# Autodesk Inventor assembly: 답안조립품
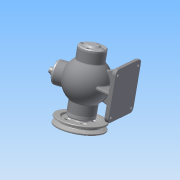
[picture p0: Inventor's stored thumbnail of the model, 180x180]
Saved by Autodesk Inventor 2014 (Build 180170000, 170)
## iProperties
Created: 2017-01
Part Number: 답안조립품
Document SubType Name: Assembly
Designer: ksu
Author: ksu
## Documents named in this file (19)
- C:\Users\ksu\Desktop\470118V1008\답안조립품.iam
- C:\Users\ksu\Desktop\470118V1008\1.본체.ipt
- C:\Users\ksu\Desktop\470118V1008\V-벨트풀리.ipt
- C:\Users\ksu\Desktop\470118V1008\너트 M8.ipt
- C:\Users\ksu\Desktop\470118V1008\뒤커버.ipt
- C:\Users\ksu\Desktop\470118V1008\멈춤링- 15 x 1.ipt
- C:\Users\ksu\Desktop\470118V1008\멈춤링- 35x1.6.ipt
- KS B 1336 - 35x1.6.ipt
- C:\Users\ksu\Desktop\470118V1008\베어링- 6202.ipt
- KS B 2023 - 6202 - 15 x 35 x 11 - 7.8.ipt
- C:\Users\ksu\Desktop\470118V1008\볼트 M4 x 12.ipt
- C:\Users\ksu\Desktop\470118V1008\볼트 M4 x 16.ipt
- C:\Users\ksu\Desktop\470118V1008\부시.ipt
- C:\Users\ksu\Desktop\470118V1008\상부커버.ipt
- C:\Users\ksu\Desktop\470118V1008\슬라이드.ipt
- C:\Users\ksu\Desktop\470118V1008\앞커버.ipt
- C:\Users\ksu\Desktop\470118V1008\오일실 15 30 7.ipt
- C:\Users\ksu\Desktop\470118V1008\키 4 x 4 x 12.ipt
- C:\Users\ksu\Desktop\470118V1008\편심축.ipt
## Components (17 placed, 6 different names)
1. 1.본체:1 — Mate:13, Mate:14, Mate:15, Mate:16, Mate:20, Mate:21, Mate:22, Mate:23, Mate:24, Mate:25, Mate:26, Mate:27
2. V-벨트풀리:1 — Mate:11, Mate:12, Mate:28, Mate:30
3. KS B 1336 - 35x1.6:1 — Mate:14, Mate:15, Mate:17
4. KS B 2023 - 6202 - 15 x 35 x 11 - 7.8:1 — Mate:5, Mate:6, Mate:8
5. KS B 1021 - 에 따름 ISO 1207 - 미터 A  M 4 x 12:1 — Insert:12
6. ISO 4762 M4 x 16:1 — Insert:2
7. KS B 2023 - 6202 - 15 x 35 x 11 - 7.8:2 — Mate:16, Mate:17, Mate:18, Mate:19
8. ISO 4762 M4 x 16:2 — Insert:3
9. ISO 4762 M4 x 16:3 — Insert:1
10. ISO 4762 M4 x 16:4 — Insert:4
11. ISO 4762 M4 x 16:5 — Insert:5
12. ISO 4762 M4 x 16:6 — Insert:6
13. ISO 4762 M4 x 16:7 — Insert:7
14. ISO 4762 M4 x 16:8 — Insert:8
15. KS B 1021 - 에 따름 ISO 1207 - 미터 A  M 4 x 12:2 — Insert:13
16. KS B 1021 - 에 따름 ISO 1207 - 미터 A  M 4 x 12:3 — Insert:9
17. KS B 1021 - 에 따름 ISO 1207 - 미터 A  M 4 x 12:4 — Insert:10
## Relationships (34: Mate 22, Insert 12)
- Mate:5: KS B 2023 - 6202 - 15 x 35 x 11 - 7.8:1
- Mate:6: KS B 2023 - 6202 - 15 x 35 x 11 - 7.8:1
- Mate:8: KS B 2023 - 6202 - 15 x 35 x 11 - 7.8:1
- Mate:11: V-벨트풀리:1
- Mate:12: V-벨트풀리:1
- Mate:13: 1.본체:1
- Mate:14: 1.본체:1 ↔ KS B 1336 - 35x1.6:1
- Mate:15: 1.본체:1 ↔ KS B 1336 - 35x1.6:1
- Mate:16: 1.본체:1 ↔ KS B 2023 - 6202 - 15 x 35 x 11 - 7.8:2
- Mate:17: KS B 1336 - 35x1.6:1 ↔ KS B 2023 - 6202 - 15 x 35 x 11 - 7.8:2
- Mate:18: KS B 2023 - 6202 - 15 x 35 x 11 - 7.8:2
- Mate:19: KS B 2023 - 6202 - 15 x 35 x 11 - 7.8:2
- Mate:20: 1.본체:1
- Mate:21: 1.본체:1
- Mate:22: 1.본체:1
- Mate:23: 1.본체:1
- Mate:24: 1.본체:1
- Mate:25: 1.본체:1
- Mate:26: 1.본체:1
- Insert:1: ISO 4762 M4 x 16:3
- Insert:2: ISO 4762 M4 x 16:1
- Insert:3: ISO 4762 M4 x 16:2
- Insert:4: ISO 4762 M4 x 16:4
- Insert:5: ISO 4762 M4 x 16:5
- Insert:6: ISO 4762 M4 x 16:6
- Insert:7: ISO 4762 M4 x 16:7
- Insert:8: ISO 4762 M4 x 16:8
- Mate:27: 1.본체:1
- Insert:9: KS B 1021 - 에 따름 ISO 1207 - 미터 A  M 4 x 12:3
- Insert:10: KS B 1021 - 에 따름 ISO 1207 - 미터 A  M 4 x 12:4
- Insert:12: KS B 1021 - 에 따름 ISO 1207 - 미터 A  M 4 x 12:1
- Mate:28: V-벨트풀리:1
- Mate:30: V-벨트풀리:1
- Insert:13: KS B 1021 - 에 따름 ISO 1207 - 미터 A  M 4 x 12:2
